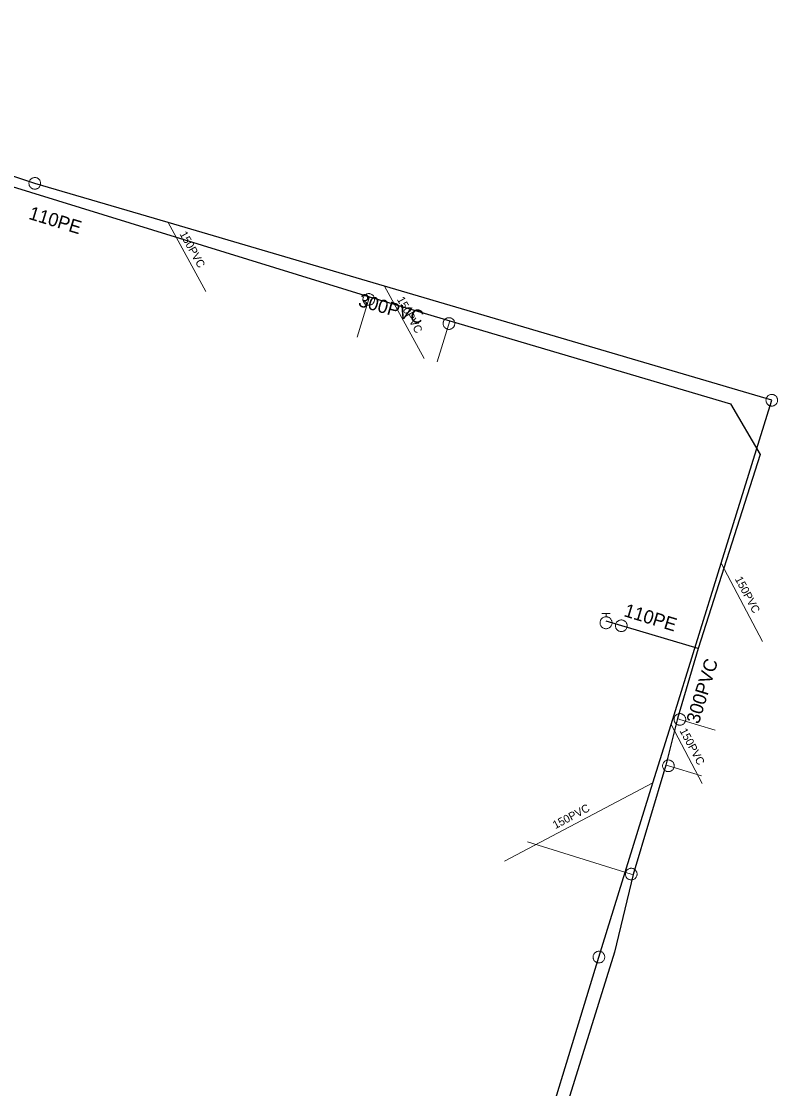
# Model space of a CAD drawing. Extents: x -741806 to -738704, y -1059275 to -1055387.
# Drawn here: x -740282.6 to -740225.9, y -1057368.6 to -1057288.6 of the extents above; entities that cross this region are included whole.
import ezdxf

# ---------------------------------------------------------------- set-up
doc = ezdxf.new("R2010")
doc.units = 0
doc.header["$LTSCALE"] = 0.4
for name, color, linetype, lineweight in [('2', 7, 'Continuous', 25), ('21', 7, 'Continuous', 13), ('3', 7, 'Continuous', 13), ('50', 7, 'Continuous', 13), ('51', 7, 'Continuous', 13), ('52', 7, 'Continuous', 25), ('56', 7, 'Continuous', 13)]:
    doc.layers.add(name, color=color, linetype=linetype, lineweight=lineweight)
for name, color, linetype in [('5', 7, 'Continuous'), ('53', 7, 'Continuous'), ('55', 7, 'Continuous')]:
    doc.layers.add(name, color=color, linetype=linetype)

msp = doc.modelspace()

# ---------------------------------------------------------------- linework, layer by layer
at = {"layer": '2'}
for points in [[(-740281.55, -1057300.75), (-740293.222, -1057296.867), (-740309.515, -1057291.446), (-740318.07, -1057288.6)], [(-740226.309, -1057317.01), (-740255.337, -1057308.466), (-740271.557, -1057303.691), (-740281.55, -1057300.75)], [(-740239.27, -1057358.76), (-740235.215, -1057345.7), (-740233.857, -1057341.325), (-740230.098, -1057329.213), (-740226.309, -1057317.01)], [(-740250.379, -1057395.179), (-740245.925, -1057380.577), (-740244.943, -1057377.361), (-740239.27, -1057358.76)]]:
    msp.add_lwpolyline(points, dxfattribs=at)
at = {"layer": '21'}
for p, q in [((-740256.463, -1057309.267), (-740257.395, -1057312.281)), ((-740250.443, -1057311.048), (-740251.399, -1057314.141))]:
    msp.add_line(p, q, dxfattribs=at)
for points in [[(-740233.366, -1057340.882), (-740233.199, -1057340.94), (-740230.541, -1057341.743)], [(-740234.254, -1057344.372), (-740234.059, -1057344.419), (-740231.578, -1057345.169)], [(-740236.702, -1057352.581), (-740236.844, -1057352.539), (-740244.618, -1057350.127)]]:
    msp.add_lwpolyline(points, dxfattribs=at)
at = {"layer": '3'}
for points in [[(-740281.97, -1057300.625), (-740281.979, -1057300.669), (-740281.985, -1057300.715), (-740281.987, -1057300.761), (-740281.983, -1057300.806), (-740281.974, -1057300.851), (-740281.962, -1057300.896), (-740281.944, -1057300.937), (-740281.922, -1057300.978), (-740281.896, -1057301.015), (-740281.866, -1057301.05), (-740281.833, -1057301.082), (-740281.796, -1057301.11), (-740281.757, -1057301.133), (-740281.716, -1057301.153), (-740281.673, -1057301.168), (-740281.628, -1057301.179), (-740281.583, -1057301.184), (-740281.537, -1057301.186), (-740281.491, -1057301.182), (-740281.446, -1057301.173), (-740281.402, -1057301.16), (-740281.361, -1057301.143), (-740281.32, -1057301.121), (-740281.282, -1057301.096), (-740281.247, -1057301.065), (-740281.217, -1057301.031), (-740281.188, -1057300.996), (-740281.164, -1057300.956), (-740281.145, -1057300.915), (-740281.13, -1057300.871), (-740281.119, -1057300.828), (-740281.113, -1057300.783), (-740281.112, -1057300.736), (-740281.116, -1057300.69), (-740281.124, -1057300.646), (-740281.137, -1057300.601), (-740281.155, -1057300.56), (-740281.177, -1057300.519), (-740281.203, -1057300.482), (-740281.232, -1057300.447), (-740281.266, -1057300.416), (-740281.302, -1057300.387), (-740281.341, -1057300.363), (-740281.382, -1057300.344), (-740281.426, -1057300.329), (-740281.47, -1057300.318), (-740281.516, -1057300.312), (-740281.561, -1057300.311), (-740281.607, -1057300.315), (-740281.652, -1057300.324), (-740281.696, -1057300.337), (-740281.738, -1057300.354), (-740281.778, -1057300.376), (-740281.816, -1057300.402), (-740281.851, -1057300.432), (-740281.883, -1057300.465), (-740281.91, -1057300.501), (-740281.934, -1057300.541), (-740281.954, -1057300.582), (-740281.969, -1057300.624)], [(-740226.178, -1057316.591), (-740226.222, -1057316.581), (-740226.267, -1057316.574), (-740226.314, -1057316.572), (-740226.358, -1057316.575), (-740226.404, -1057316.583), (-740226.449, -1057316.595), (-740226.491, -1057316.613), (-740226.532, -1057316.633), (-740226.569, -1057316.66), (-740226.604, -1057316.688), (-740226.636, -1057316.721), (-740226.665, -1057316.757), (-740226.689, -1057316.796), (-740226.71, -1057316.837), (-740226.725, -1057316.88), (-740226.737, -1057316.925), (-740226.743, -1057316.97), (-740226.745, -1057317.015), (-740226.742, -1057317.061), (-740226.734, -1057317.107), (-740226.721, -1057317.15), (-740226.705, -1057317.192), (-740226.683, -1057317.233), (-740226.658, -1057317.272), (-740226.629, -1057317.307), (-740226.595, -1057317.338), (-740226.56, -1057317.367), (-740226.521, -1057317.392), (-740226.48, -1057317.412), (-740226.437, -1057317.427), (-740226.393, -1057317.439), (-740226.348, -1057317.445), (-740226.301, -1057317.447), (-740226.255, -1057317.444), (-740226.211, -1057317.437), (-740226.167, -1057317.424), (-740226.125, -1057317.407), (-740226.083, -1057317.385), (-740226.046, -1057317.36), (-740226.011, -1057317.331), (-740225.979, -1057317.298), (-740225.95, -1057317.262), (-740225.925, -1057317.224), (-740225.905, -1057317.183), (-740225.89, -1057317.139), (-740225.878, -1057317.095), (-740225.871, -1057317.05), (-740225.87, -1057317.004), (-740225.873, -1057316.958), (-740225.881, -1057316.913), (-740225.894, -1057316.869), (-740225.91, -1057316.826), (-740225.932, -1057316.786), (-740225.957, -1057316.748), (-740225.987, -1057316.713), (-740226.019, -1057316.68), (-740226.055, -1057316.653), (-740226.094, -1057316.628), (-740226.135, -1057316.608), (-740226.177, -1057316.592)], [(-740239.141, -1057358.341), (-740239.185, -1057358.33), (-740239.23, -1057358.324), (-740239.277, -1057358.322), (-740239.322, -1057358.325), (-740239.367, -1057358.334), (-740239.412, -1057358.346), (-740239.453, -1057358.364), (-740239.494, -1057358.385), (-740239.532, -1057358.411), (-740239.567, -1057358.44), (-740239.599, -1057358.473), (-740239.628, -1057358.509), (-740239.651, -1057358.548), (-740239.672, -1057358.589), (-740239.687, -1057358.632), (-740239.699, -1057358.677), (-740239.704, -1057358.722), (-740239.706, -1057358.767), (-740239.703, -1057358.813), (-740239.694, -1057358.859), (-740239.682, -1057358.902), (-740239.665, -1057358.944), (-740239.643, -1057358.985), (-740239.618, -1057359.023), (-740239.588, -1057359.059), (-740239.555, -1057359.09), (-740239.52, -1057359.118), (-740239.48, -1057359.143), (-740239.439, -1057359.163), (-740239.396, -1057359.178), (-740239.352, -1057359.189), (-740239.307, -1057359.196), (-740239.26, -1057359.197), (-740239.214, -1057359.194), (-740239.17, -1057359.186), (-740239.126, -1057359.174), (-740239.084, -1057359.156), (-740239.042, -1057359.134), (-740239.005, -1057359.109), (-740238.97, -1057359.08), (-740238.938, -1057359.047), (-740238.91, -1057359.01), (-740238.885, -1057358.972), (-740238.865, -1057358.931), (-740238.85, -1057358.887), (-740238.839, -1057358.843), (-740238.832, -1057358.798), (-740238.831, -1057358.752), (-740238.834, -1057358.706), (-740238.843, -1057358.661), (-740238.855, -1057358.617), (-740238.872, -1057358.575), (-740238.894, -1057358.534), (-740238.919, -1057358.496), (-740238.949, -1057358.461), (-740238.982, -1057358.429), (-740239.018, -1057358.401), (-740239.057, -1057358.377), (-740239.098, -1057358.357), (-740239.14, -1057358.341)]]:
    msp.add_lwpolyline(points, dxfattribs=at)
at = {"layer": '50'}
for p in [(-740239.04, -1057332.989), (-740238.732, -1057333.242), (-740238.421, -1057332.989)]:
    msp.add_line(p, (-740238.732, -1057332.989), dxfattribs=at)
msp.add_lwpolyline([(-740238.284, -1057333.696), (-740238.285, -1057333.647), (-740238.292, -1057333.602), (-740238.304, -1057333.555), (-740238.319, -1057333.512), (-740238.338, -1057333.47), (-740238.365, -1057333.43), (-740238.397, -1057333.395), (-740238.428, -1057333.359), (-740238.465, -1057333.328), (-740238.506, -1057333.304), (-740238.547, -1057333.282), (-740238.589, -1057333.263), (-740238.635, -1057333.254), (-740238.682, -1057333.245), (-740238.728, -1057333.242), (-740238.773, -1057333.245), (-740238.821, -1057333.249), (-740238.868, -1057333.263), (-740238.91, -1057333.281), (-740238.955, -1057333.301), (-740238.993, -1057333.326), (-740239.031, -1057333.356), (-740239.064, -1057333.39), (-740239.093, -1057333.425), (-740239.12, -1057333.464), (-740239.141, -1057333.505), (-740239.158, -1057333.55), (-740239.174, -1057333.595), (-740239.178, -1057333.642), (-740239.183, -1057333.688), (-740239.181, -1057333.737), (-740239.174, -1057333.784), (-740239.162, -1057333.827), (-740239.146, -1057333.873), (-740239.123, -1057333.914), (-740239.1, -1057333.954), (-740239.068, -1057333.99), (-740239.037, -1057334.024), (-740238.999, -1057334.055), (-740238.961, -1057334.08), (-740238.916, -1057334.102), (-740238.874, -1057334.118), (-740238.83, -1057334.132), (-740238.781, -1057334.14), (-740238.734, -1057334.143), (-740238.687, -1057334.14), (-740238.643, -1057334.132), (-740238.597, -1057334.12), (-740238.552, -1057334.104), (-740238.509, -1057334.082), (-740238.47, -1057334.058), (-740238.433, -1057334.028), (-740238.4, -1057333.996), (-740238.371, -1057333.96), (-740238.346, -1057333.919), (-740238.32, -1057333.878), (-740238.305, -1057333.835), (-740238.293, -1057333.788), (-740238.285, -1057333.743)], close=True, dxfattribs=at)
at = {"layer": '51'}
for points in [[(-740256.081, -1057309.448), (-740256.083, -1057309.403), (-740256.09, -1057309.358), (-740256.102, -1057309.313), (-740256.118, -1057309.271), (-740256.139, -1057309.23), (-740256.164, -1057309.191), (-740256.193, -1057309.156), (-740256.225, -1057309.123), (-740256.261, -1057309.095), (-740256.299, -1057309.07), (-740256.34, -1057309.049), (-740256.383, -1057309.032), (-740256.427, -1057309.02), (-740256.472, -1057309.013), (-740256.518, -1057309.011), (-740256.564, -1057309.013), (-740256.609, -1057309.02), (-740256.653, -1057309.032), (-740256.696, -1057309.049), (-740256.737, -1057309.07), (-740256.775, -1057309.095), (-740256.811, -1057309.123), (-740256.843, -1057309.156), (-740256.872, -1057309.191), (-740256.897, -1057309.23), (-740256.918, -1057309.271), (-740256.934, -1057309.313), (-740256.946, -1057309.358), (-740256.953, -1057309.403), (-740256.956, -1057309.449), (-740256.953, -1057309.494), (-740256.946, -1057309.539), (-740256.934, -1057309.584), (-740256.918, -1057309.626), (-740256.897, -1057309.667), (-740256.872, -1057309.706), (-740256.843, -1057309.741), (-740256.811, -1057309.774), (-740256.775, -1057309.802), (-740256.737, -1057309.827), (-740256.696, -1057309.848), (-740256.653, -1057309.865), (-740256.609, -1057309.876), (-740256.564, -1057309.884), (-740256.518, -1057309.886), (-740256.472, -1057309.884), (-740256.427, -1057309.876), (-740256.383, -1057309.865), (-740256.34, -1057309.848), (-740256.299, -1057309.827), (-740256.261, -1057309.802), (-740256.225, -1057309.774), (-740256.193, -1057309.741), (-740256.164, -1057309.706), (-740256.139, -1057309.667), (-740256.118, -1057309.626), (-740256.102, -1057309.584), (-740256.09, -1057309.539), (-740256.083, -1057309.494), (-740256.081, -1057309.449)], [(-740250.07, -1057311.257), (-740250.071, -1057311.212), (-740250.079, -1057311.167), (-740250.091, -1057311.122), (-740250.107, -1057311.08), (-740250.128, -1057311.039), (-740250.152, -1057311), (-740250.182, -1057310.965), (-740250.214, -1057310.932), (-740250.25, -1057310.904), (-740250.288, -1057310.879), (-740250.329, -1057310.858), (-740250.372, -1057310.841), (-740250.416, -1057310.829), (-740250.461, -1057310.822), (-740250.507, -1057310.82), (-740250.553, -1057310.822), (-740250.598, -1057310.829), (-740250.642, -1057310.841), (-740250.684, -1057310.858), (-740250.726, -1057310.879), (-740250.764, -1057310.904), (-740250.799, -1057310.932), (-740250.831, -1057310.965), (-740250.861, -1057311), (-740250.886, -1057311.039), (-740250.907, -1057311.08), (-740250.923, -1057311.122), (-740250.934, -1057311.167), (-740250.942, -1057311.212), (-740250.945, -1057311.258), (-740250.942, -1057311.303), (-740250.934, -1057311.348), (-740250.923, -1057311.393), (-740250.907, -1057311.435), (-740250.886, -1057311.476), (-740250.861, -1057311.515), (-740250.831, -1057311.55), (-740250.799, -1057311.583), (-740250.764, -1057311.611), (-740250.726, -1057311.636), (-740250.684, -1057311.657), (-740250.642, -1057311.674), (-740250.598, -1057311.685), (-740250.553, -1057311.693), (-740250.507, -1057311.695), (-740250.461, -1057311.693), (-740250.416, -1057311.685), (-740250.372, -1057311.674), (-740250.329, -1057311.657), (-740250.288, -1057311.636), (-740250.25, -1057311.611), (-740250.214, -1057311.583), (-740250.182, -1057311.55), (-740250.152, -1057311.515), (-740250.128, -1057311.476), (-740250.107, -1057311.435), (-740250.091, -1057311.393), (-740250.079, -1057311.348), (-740250.071, -1057311.303), (-740250.07, -1057311.258)], [(-740237.151, -1057333.916), (-740237.152, -1057333.871), (-740237.16, -1057333.826), (-740237.172, -1057333.781), (-740237.188, -1057333.739), (-740237.209, -1057333.698), (-740237.233, -1057333.659), (-740237.263, -1057333.624), (-740237.295, -1057333.591), (-740237.331, -1057333.563), (-740237.369, -1057333.538), (-740237.41, -1057333.517), (-740237.453, -1057333.5), (-740237.497, -1057333.488), (-740237.542, -1057333.481), (-740237.588, -1057333.479), (-740237.634, -1057333.481), (-740237.679, -1057333.488), (-740237.723, -1057333.5), (-740237.766, -1057333.517), (-740237.807, -1057333.538), (-740237.845, -1057333.563), (-740237.88, -1057333.591), (-740237.913, -1057333.624), (-740237.942, -1057333.659), (-740237.967, -1057333.698), (-740237.988, -1057333.739), (-740238.004, -1057333.781), (-740238.016, -1057333.826), (-740238.023, -1057333.871), (-740238.026, -1057333.917), (-740238.023, -1057333.962), (-740238.016, -1057334.007), (-740238.004, -1057334.052), (-740237.988, -1057334.094), (-740237.967, -1057334.135), (-740237.942, -1057334.174), (-740237.913, -1057334.209), (-740237.88, -1057334.242), (-740237.845, -1057334.27), (-740237.807, -1057334.295), (-740237.766, -1057334.316), (-740237.723, -1057334.333), (-740237.679, -1057334.344), (-740237.634, -1057334.352), (-740237.588, -1057334.354), (-740237.542, -1057334.352), (-740237.497, -1057334.344), (-740237.453, -1057334.333), (-740237.41, -1057334.316), (-740237.369, -1057334.295), (-740237.331, -1057334.27), (-740237.295, -1057334.242), (-740237.263, -1057334.209), (-740237.233, -1057334.174), (-740237.209, -1057334.135), (-740237.188, -1057334.094), (-740237.172, -1057334.052), (-740237.16, -1057334.007), (-740237.152, -1057333.962), (-740237.151, -1057333.917)], [(-740232.762, -1057340.94), (-740232.764, -1057340.895), (-740232.771, -1057340.85), (-740232.783, -1057340.805), (-740232.799, -1057340.763), (-740232.82, -1057340.722), (-740232.845, -1057340.683), (-740232.874, -1057340.648), (-740232.906, -1057340.615), (-740232.942, -1057340.587), (-740232.98, -1057340.562), (-740233.021, -1057340.541), (-740233.064, -1057340.524), (-740233.108, -1057340.512), (-740233.153, -1057340.505), (-740233.199, -1057340.503), (-740233.245, -1057340.505), (-740233.29, -1057340.512), (-740233.334, -1057340.524), (-740233.377, -1057340.541), (-740233.418, -1057340.562), (-740233.456, -1057340.587), (-740233.492, -1057340.615), (-740233.524, -1057340.648), (-740233.553, -1057340.683), (-740233.578, -1057340.722), (-740233.599, -1057340.763), (-740233.615, -1057340.805), (-740233.627, -1057340.85), (-740233.634, -1057340.895), (-740233.637, -1057340.941), (-740233.634, -1057340.986), (-740233.627, -1057341.031), (-740233.615, -1057341.076), (-740233.599, -1057341.118), (-740233.578, -1057341.159), (-740233.553, -1057341.198), (-740233.524, -1057341.233), (-740233.492, -1057341.266), (-740233.456, -1057341.294), (-740233.418, -1057341.319), (-740233.377, -1057341.34), (-740233.334, -1057341.357), (-740233.29, -1057341.368), (-740233.245, -1057341.376), (-740233.199, -1057341.378), (-740233.153, -1057341.376), (-740233.108, -1057341.368), (-740233.064, -1057341.357), (-740233.021, -1057341.34), (-740232.98, -1057341.319), (-740232.942, -1057341.294), (-740232.906, -1057341.266), (-740232.874, -1057341.233), (-740232.845, -1057341.198), (-740232.82, -1057341.159), (-740232.799, -1057341.118), (-740232.783, -1057341.076), (-740232.771, -1057341.031), (-740232.764, -1057340.986), (-740232.762, -1057340.941)], [(-740233.622, -1057344.419), (-740233.624, -1057344.374), (-740233.631, -1057344.329), (-740233.643, -1057344.284), (-740233.659, -1057344.242), (-740233.68, -1057344.201), (-740233.705, -1057344.162), (-740233.734, -1057344.127), (-740233.766, -1057344.094), (-740233.802, -1057344.066), (-740233.84, -1057344.041), (-740233.881, -1057344.02), (-740233.924, -1057344.003), (-740233.968, -1057343.991), (-740234.013, -1057343.984), (-740234.059, -1057343.982), (-740234.105, -1057343.984), (-740234.15, -1057343.991), (-740234.194, -1057344.003), (-740234.237, -1057344.02), (-740234.278, -1057344.041), (-740234.316, -1057344.066), (-740234.352, -1057344.094), (-740234.384, -1057344.127), (-740234.413, -1057344.162), (-740234.438, -1057344.201), (-740234.459, -1057344.242), (-740234.475, -1057344.284), (-740234.487, -1057344.329), (-740234.494, -1057344.374), (-740234.497, -1057344.42), (-740234.494, -1057344.465), (-740234.487, -1057344.51), (-740234.475, -1057344.555), (-740234.459, -1057344.597), (-740234.438, -1057344.638), (-740234.413, -1057344.677), (-740234.384, -1057344.712), (-740234.352, -1057344.745), (-740234.316, -1057344.773), (-740234.278, -1057344.798), (-740234.237, -1057344.819), (-740234.194, -1057344.836), (-740234.15, -1057344.847), (-740234.105, -1057344.855), (-740234.059, -1057344.857), (-740234.013, -1057344.855), (-740233.968, -1057344.847), (-740233.924, -1057344.836), (-740233.881, -1057344.819), (-740233.84, -1057344.798), (-740233.802, -1057344.773), (-740233.766, -1057344.745), (-740233.734, -1057344.712), (-740233.705, -1057344.677), (-740233.68, -1057344.638), (-740233.659, -1057344.597), (-740233.643, -1057344.555), (-740233.631, -1057344.51), (-740233.624, -1057344.465), (-740233.622, -1057344.42)], [(-740236.407, -1057352.539), (-740236.409, -1057352.494), (-740236.416, -1057352.449), (-740236.428, -1057352.404), (-740236.444, -1057352.362), (-740236.465, -1057352.321), (-740236.49, -1057352.282), (-740236.519, -1057352.247), (-740236.551, -1057352.214), (-740236.587, -1057352.186), (-740236.625, -1057352.161), (-740236.666, -1057352.14), (-740236.709, -1057352.123), (-740236.753, -1057352.111), (-740236.798, -1057352.104), (-740236.844, -1057352.102), (-740236.89, -1057352.104), (-740236.935, -1057352.111), (-740236.979, -1057352.123), (-740237.022, -1057352.14), (-740237.063, -1057352.161), (-740237.101, -1057352.186), (-740237.137, -1057352.214), (-740237.169, -1057352.247), (-740237.198, -1057352.282), (-740237.223, -1057352.321), (-740237.244, -1057352.362), (-740237.26, -1057352.404), (-740237.272, -1057352.449), (-740237.279, -1057352.494), (-740237.282, -1057352.54), (-740237.279, -1057352.585), (-740237.272, -1057352.63), (-740237.26, -1057352.675), (-740237.244, -1057352.717), (-740237.223, -1057352.758), (-740237.198, -1057352.797), (-740237.169, -1057352.832), (-740237.137, -1057352.865), (-740237.101, -1057352.893), (-740237.063, -1057352.918), (-740237.022, -1057352.939), (-740236.979, -1057352.956), (-740236.935, -1057352.967), (-740236.89, -1057352.975), (-740236.844, -1057352.977), (-740236.798, -1057352.975), (-740236.753, -1057352.967), (-740236.709, -1057352.956), (-740236.666, -1057352.939), (-740236.625, -1057352.918), (-740236.587, -1057352.893), (-740236.551, -1057352.865), (-740236.519, -1057352.832), (-740236.49, -1057352.797), (-740236.465, -1057352.758), (-740236.444, -1057352.717), (-740236.428, -1057352.675), (-740236.416, -1057352.63), (-740236.409, -1057352.585), (-740236.407, -1057352.54)]]:
    msp.add_lwpolyline(points, dxfattribs=at)
at = {"layer": '52'}
msp.add_line((-740231.828, -1057335.632), (-740238.719, -1057333.58), dxfattribs=at)
msp.add_lwpolyline([(-740319.489, -1057289.497), (-740317.443, -1057290.145), (-740295.568, -1057297.09), (-740289.021, -1057299.219), (-740256.463, -1057309.267), (-740250.443, -1057311.048), (-740229.41, -1057317.267), (-740227.171, -1057321.081), (-740231.828, -1057335.632), (-740233.366, -1057340.882), (-740234.254, -1057344.372), (-740236.702, -1057352.581), (-740238.107, -1057358.402), (-740245.175, -1057381.093), (-740246.118, -1057383.663), (-740249.21, -1057392.7), (-740249.383, -1057395.375), (-740249.71, -1057396.29)], dxfattribs=at)
at = {"layer": '56'}
for p, q in [((-740268.739, -1057308.86), (-740271.557, -1057303.691)), ((-740252.377, -1057313.892), (-740255.337, -1057308.466)), ((-740227, -1057335.1), (-740230.098, -1057329.213)), ((-740231.53, -1057345.75), (-740233.857, -1057341.325)), ((-740246.35, -1057351.56), (-740235.215, -1057345.7))]:
    msp.add_line(p, q, dxfattribs=at)

# ---------------------------------------------------------------- texts
at = {"layer": '5'}
for rotation, p in [(344, (-740257.368, -1057309.937)), (73, (-740231.782, -1057341.338))]:
    msp.add_text('300PVC', height=1, rotation=rotation, dxfattribs=at).set_placement(p)
at = {"layer": '53'}
for p in [(-740282.074, -1057303.401), (-740237.459, -1057333.187)]:
    msp.add_text('110PE ', height=1, rotation=343, dxfattribs=at).set_placement(p)
at = {"layer": '55'}
for rotation, p in [(299, (-740270.719, -1057304.536)), (299, (-740254.428, -1057309.44)), (298, (-740229.093, -1057330.408)), (298, (-740233.238, -1057341.79)), (28, (-740242.529, -1057349.175))]:
    msp.add_text('150PVC', height=0.6, rotation=rotation, dxfattribs=at).set_placement(p)

doc.saveas('drawing.dxf')
